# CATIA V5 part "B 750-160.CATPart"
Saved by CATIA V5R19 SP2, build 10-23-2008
Part number: B 750-160
Bounding box of the stored display mesh (mm): x -22.494 to 22.494, y -22.494 to 22.494, z 0 to 405
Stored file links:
  C:\Users\Bora\Desktop\3D Katı model\B serisi\B 750\B 750-160.CATPart
  C:\Program Files\Dassault Systemes\B19\intel_a\reffiles\standard\MetricThickPitch.txt
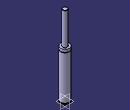
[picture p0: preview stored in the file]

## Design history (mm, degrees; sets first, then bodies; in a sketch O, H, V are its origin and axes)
Body1 (main body)
  Sketch1 on yz-plane, origin (0, 0, 0), H (0, 1, 0), V (0, 0, 1)
    point P3 (12, 404)
    point P5 (12, 404)
    point P7 (22.5, 229.5)
    point P8 (22.5, 227.5)
    point P12 (22.5, 227.5)
    point P13 (22.5, 229.5)
    line L1 (22.5, 0) -> (22.5, 4)
    line L2 (12, 404) -> (12, 243)
    arc A1 centre (11, 404) radius 1 from (12, 404) to (11, 405) ccw
    arc A2 centre (22.5, 228.5) radius 1 from (22.5, 229.5) to (22.5, 227.5) ccw
    line L3 (20, 7.5) -> (20, 4)
    line L4 (22.5, 7.5) -> (22.5, 227.5)
    line L5 (22.5, 229.5) -> (22.5, 243)
    line L6 (11, 405) -> (0, 405)
    point P15 (0, 405)
    line L7 (12, 243) -> (22.5, 243)
    line L8 (0, 0) -> (22.5, 0)
    line L9 (20, 7.5) -> (22.5, 7.5)
    line L10 (20, 4) -> (22.5, 4)
    coincidence: P15 V, P3 P5, P7 P13, P8 P12
    tangency: L6 A1
    horizontal: L7 H, L8 H, L9 H, L10 H
  Shaft1: profile Sketch1, axis Sketch1.V, angle 360
  Sketch2 on face of Shaft1 from Sketch1.L8, origin (0, 0, 0), H (1, 0, 0), V (0, -1, 0)
    point P1 (10, 0)
    distance P1 V = 10
  Hole1: placed by Sketch2, at (10, 0, 0) direction (0, 0, 1), diameter 6.647, depth 13, threaded "M8", thread diameter 8, thread depth 13, pitch 1.25
  CircPattern1: of Hole1, instances 2, angular step 180, axis from xy-plane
